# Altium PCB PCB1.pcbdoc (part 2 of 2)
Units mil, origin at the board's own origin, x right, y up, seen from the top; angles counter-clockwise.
Board outline 4044 x 3540 mil, 2 copper layers (Top Layer, Bottom Layer), stack 2.756 mil thick; 143 components, 117 nets, 519 pads, 194 vias.
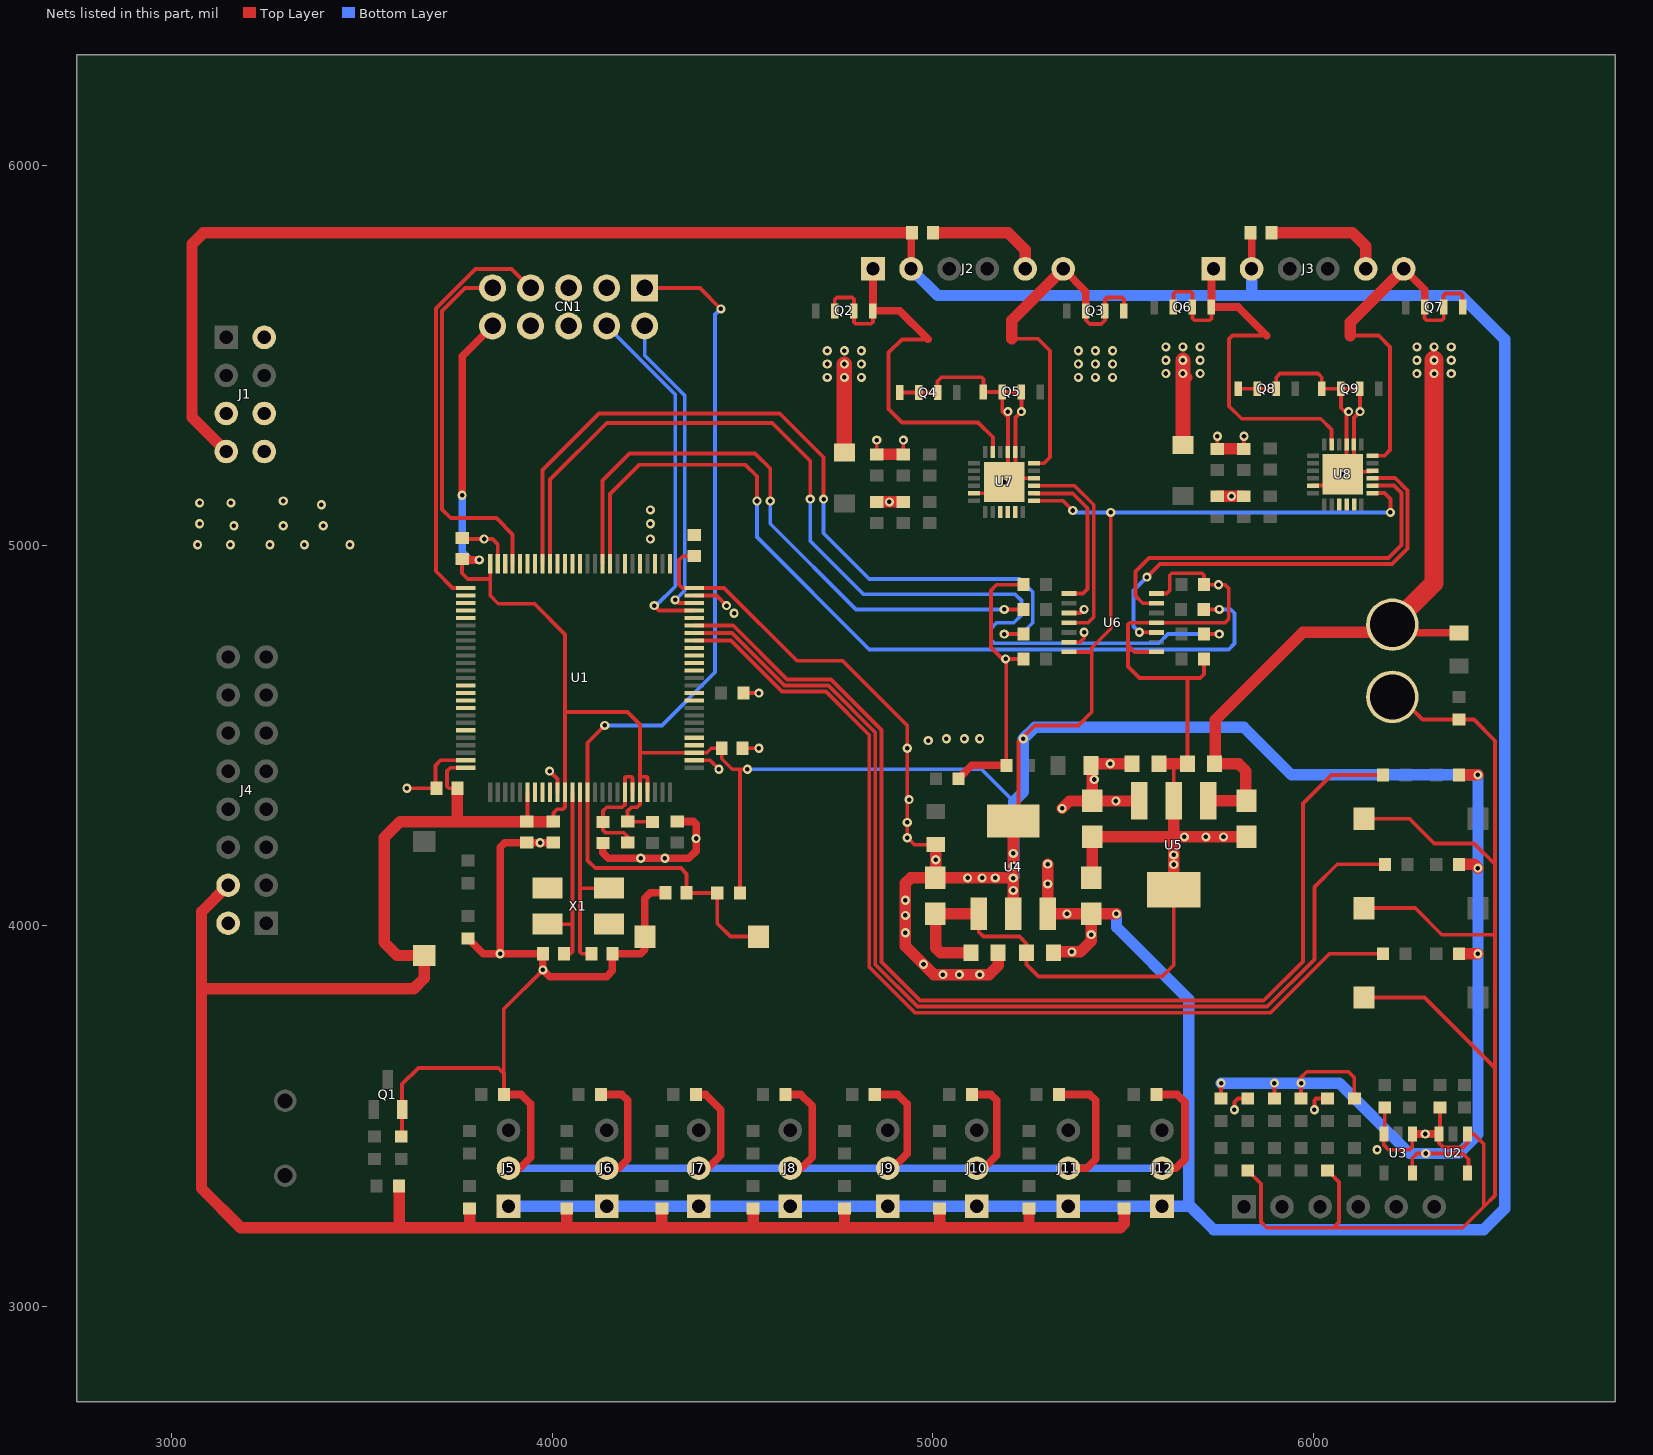
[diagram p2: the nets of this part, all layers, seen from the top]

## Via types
v1: diameter 24.02, hole 12.01, Top Layer to Bottom Layer, 194 vias

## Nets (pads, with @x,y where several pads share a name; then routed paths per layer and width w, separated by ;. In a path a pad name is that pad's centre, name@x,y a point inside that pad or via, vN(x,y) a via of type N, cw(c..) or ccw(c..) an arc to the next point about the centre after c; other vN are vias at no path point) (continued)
GND: C1.2 C2.1 C3.2 C4.2 C5.2 C6.2 C7.2 C8.1 C9.1 C10.1 C12.2 C13.2 C14.2 C15.1 C16.1 C17.2 C18.1 C19.2 C20.2 C21.1 C22.1 C23.1 C26.2 C27.2 C28.1 C29.1 C32.2 C33.2 CN1.6 CN1.8 CN2.1 J1.5 J1.6 J2.5 J3.5 J4.2 J5.2 J6.2 J7.2 J8.2 J9.2 J10.2 J11.2 J12.2 L1.1 Q1.2 Q4.1 Q4.2 Q4.3 Q5.1 Q5.2 Q5.3 Q8.1 Q8.2 Q8.3 Q9.1 Q9.2 Q9.3 R1.1 R4.2 R7.1 R8.2 R11.1 R16.1 R17.1 R18.1 R25.2 R26.1 R27.2 R28.1 R35.1 R36.1 R37.1 R44.1 R45.1 R46.1 R53.1 R54.1 R55.1 R62.1 R63.1 R64.1 SW2.2 SW3.1 SW4.1 SW5.1 U1.10 U1.27 U1.49 U1.74 U1.99 U2.1 U2.3 U3.1 U3.3 U4.1 U5.2 U5.4 U6.1 U6.4 U6.7 U6.10 U6.13 U7.5 U7.16 U7.20 U7.21 U7.25 U8.5 U8.16 U8.20 U8.21 U8.25 | length 19107.5
  Top Layer w10: R11.1@3603,3447 3605.4,3449.4 Q1.2@3605.4,3517.63 3605.4,3584.4 3648,3627 3858,3627 3872.66,3612.34 ; v1(3618,4362) C5.2@3695.44,4362 3693,4364.44 3693,4422 3706.46,4435.46 U1.99@3772.67,4435.46 ; C1.2@3763,5019.56 3765.56,5017 v1(3820.68,5017) 3843,5017 3856.47,5003.53 U1.74@3856.47,4952.33 ; v1(3975.44,3884.56) 3872.66,3781.78 3872.66,3612.34 ; v1(3993,4407) 4013.95,4386.05 U1.10@4013.95,4351.67 ; U1.27@4373.33,4435.46 4414.54,4435.46 v1(4438,4412) ; U1.49@4373.33,4868.53 4431.47,4868.53 v1(4458,4842) ; C4.2@4500.56,4467 v1(4543,4467) ; R7.1@4502.66,4612 v1(4543,4612) ; C23.1@4852.63,5239.44 4853,5239.81 v1(4853,5277) ; Q4.1@4912.63,5402 Q4.2@4962.63,5402 Q4.3@5012.63,5402 5012.63,5431.63 5023,5442 5128,5442 5133,5437 5133,5403.87 Q5.1@5132.63,5403.5 Q5.2@5182.63,5403.5 ; C22.1@4922.63,5239.44 4922.63,5276.63 v1(4923,5277) ; U7.5@5108.95,5137.37 5158.12,5137.37 v1(5187.63,5166.88) 5197.52,5176.77 U7.16@5266.43,5176.77 ; U4.1@5121.02,4032.09 5121.02,3983.98 5133,3972 5228,3972 5246.57,3953.43 C15.1@5246.57,3929.09 5246.57,3898.43 5278,3867 5603,3867 5633.41,3897.41 U5.4@5633.41,4095.2 ; R17.1@5193.34,4422 5193.34,4691.66 v1@5183,4702 ; R26.1@5238.34,4702 v1@5183,4702 ; R28.1@5238.34,4897 5168,4897 5153,4882 5153,4732 v1@5183,4702 ; U6.13@5357.84,4745.82 5386.82,4745.82 5398,4757 v1(5398,4772) ; U6.10@5357.84,4822.59 5388.59,4822.59 v1(5398,4832) ; U6.1@5588.16,4720.23 5529.77,4720.23 5513,4737 ; U6.7@5588.16,4873.77 5614.77,4873.77 5623,4882 5623,4922 5628,4927 5708,4927 5713,4922 5713,4897.34 R27.2@5712.66,4897 v1(5751.12,4897) 5768,4897 5778,4887 5778,4807 5768,4797 U6.4@5588.16,4797 5518,4797 5513,4792 5513,4737 ; 5631.97,4426.25 5633.41,4424.81 U5.2@5633.41,4329.05 ; C18.1@5669.2,4426.25 5669.2,4649.8 5666.99,4652 ; R25.2@5712.66,4702 5712.66,4661.66 5703,4652 5666.99,4652 ; C29.1@5747.42,5253.83 5748,5254.41 v1(5748,5287) ; v1(5793,3517) 5793,3537 5802.66,3546.66 R55.1@5828,3546.66 ; Q8.1@5802.63,5412 Q8.2@5852.63,5412 Q8.3@5902.63,5412 5902.63,5441.63 5913,5452 6013,5452 6022.63,5442.37 Q9.1@6022.63,5412 Q9.2@6072.63,5412 ; C28.1@5817.42,5253.83 5817.42,5286.42 v1(5818,5287) ; R62.1@5828,3357.34 5863,3322.34 5863,3222 5878,3207 6053,3207 ; U8.5@5998.89,5157.33 6048.06,5157.33 v1(6077.57,5186.84) U8.25@6084.72,5193.99 ; v1(6003,3517) 6003,3542 6007.66,3546.66 R64.1@6038,3546.66 ; R63.1@6038,3357.34 6068,3327.34 6068,3222 6053,3207 ; SW3.1@6133.4,3812 6292.41,3812 6478,3626.41 ; SW4.1@6133.4,4047 6268,4047 6338,3977 6478,3977 ; SW5.1@6133.4,4282 6253,4282 6318,4217 6423,4217 6478,4162 ; U8.16@6156.37,5196.73 6153.63,5193.99 U8.25@6084.72,5193.99 ; R8.2@6188,3522.34 6188,3455.59 U3.3@6185.6,3453.18 6185.6,3424.4 6198,3412 6253,3412 6260.4,3419.4 U3.1@6260.4,3453.18 ; CN2.1@6208,4622 6287.66,4542.34 R16.1@6383,4542.34 6422.66,4542.34 6478,4487 6478,4162 ; R4.2@6333,3522.68 6333,3455.59 U2.3@6330.6,3453.18 6330.6,3429.4 6342,3418 6394,3418 6405.4,3429.4 U2.1@6405.4,3453.18 6421.81,3453.18 6448,3427 6448,3262 ; 3872.66,3612.34 R35.1@3872.66,3557 3873,3557.34 3873,3612 3872.66,3612.34 ; Q5.2@5182.63,5403.5 Q5.3@5232.63,5403.5 5233,5403.13 v1(5233,5352) 5217.21,5336.21 U7.20@5217.21,5245.68 5217.21,5196.46 5197.56,5176.81 U7.21@5197.56,5245.68 5197.56,5337.44 5182.63,5352.37 Q5.2@5182.63,5403.5 ; 5513,4737 5513,4682 5543,4652 5666.99,4652 ; 6053,3207 6393,3207 6448,3262 ; Q9.2@6072.63,5412 Q9.3@6122.63,5412 6123,5411.63 v1(6123,5352) 6107.15,5336.15 U8.20@6107.15,5265.64 6107.15,5216.42 U8.25@6087.5,5196.77 ; Q9.2@6072.63,5412 6073,5411.63 6073,5362 6087.5,5347.5 U8.21@6087.5,5265.64 U8.25@6087.5,5196.77 ; U8.25@6084.72,5193.99 U8.25@6087.5,5196.77 ; 6448,3262 6478,3292 6478,3626.41 ; 6478,3626.41 6478,3977 ; 6478,3977 6478,4162
  Top Layer w20: R1.1@3778,3967.34 3818.34,3927 v1(3863,3927) ; R35.1@3872.66,3557 3918,3557 3943,3532 3943,3392 3914.15,3363.15 J5.2@3885,3363.15 ; C7.2@4003,4218.83 v1(3967.93,4218.83) C6.2@3933,4218.83 3874.83,4218.83 3863,4207 v1(3863,3927) ; R36.1@4128,3557 4183,3557 4198,3542 4198,3387 4174.15,3363.15 J6.2@4143.42,3363.15 ; L1.1@4133,4218.18 4133,4192 4147,4178 v1(4232.58,4178) v1(4295.89,4178) 4359,4178 4378,4197 v1(4378,4229.95) 4378,4267 4370.44,4274.56 C12.2@4328,4274.56 ; C13.2@4298,4087 4258,4087 4243.4,4072.4 SW2.2@4243.4,3972 4243.4,3937.4 4233,3927 C8.1@4158.12,3927 4158.12,3882.12 4143,3867 3993,3867 v1(3975.44,3884.56) C2.1@3975.44,3927 v1(3863,3927) ; R37.1@4377.32,3557 4403,3557 4443,3517 4443,3397 4409.15,3363.15 J7.2@4384.57,3363.15 ; R44.1@4612.66,3557 4653,3557 4683,3527 4683,3392 4654.15,3363.15 J8.2@4625.72,3363.15 ; R45.1@4847.66,3557 4908,3557 4933,3532 4933,3402 4894.15,3363.15 J9.2@4881.61,3363.15 ; R18.1@5067.66,4387 5102.66,4422 R17.1@5193.34,4422 ; R46.1@5102.66,3557 5153,3557 5168,3542 5168,3397 5134.15,3363.15 J10.2@5115.29,3363.15 ; R53.1@5332.32,3557 5413,3557 5428,3542 5428,3387 5404.15,3363.15 J11.2@5356.43,3363.15 ; R54.1@5587.66,3557 5643,3557 5663,3537 5663,3387 5639.15,3363.15 J12.2@5602.58,3363.15 ; U3.1@6260.4,3453.18 v1(6294.63,3453.18) U2.3@6330.6,3453.18
  Top Layer w30: C27.2@4852.63,5114.44 v1(4885.89,5114.44) C26.2@4922.63,5114.44 ; C23.1@4852.63,5239.44 C22.1@4922.63,5239.44 ; C9.1@5000.56,5822 5198,5822 5243,5777 J2.5@5243,5727 ; C16.1@5101.14,3929.09 5020.9,3929.09 5008,3942 5008,4030.43 C17.2@5006.57,4031.86 5120.78,4031.86 U4.1@5121.02,4032.09 ; C14.2@5416.57,4126.34 5419.63,4129.4 C20.2@5419.63,4234.01 5633.41,4234.01 ; C21.1@5594.63,4426.25 5631.97,4426.25 C18.1@5669.2,4426.25 ; U5.4@5633.41,4095.2 v1(5633.41,4161.53) v1(5633.41,4186.96) 5633.41,4234.01 ; U5.2@5633.41,4329.05 5633.41,4234.01 ; C29.1@5747.42,5253.83 C28.1@5817.42,5253.83 ; C33.2@5747.63,5129.44 v1(5785.22,5129.44) C32.2@5817.63,5129.44 ; C19.2@5824.63,4234.01 v1(5764.16,4234.01) v1(5717.98,4234.01) v1(5661.42,4234.01) 5633.41,4234.01 ; C10.1@5890.56,5822 6103,5822 6138,5787 J3.5@6138,5727
  Bottom Layer w20: J5.2@3885,3363.15 J6.2@4143.42,3363.15 J7.2@4384.57,3363.15 J8.2@4625.72,3363.15 J9.2@4881.61,3363.15 J10.2@5115.29,3363.15 J11.2@5356.43,3363.15 J12.2@5602.58,3363.15
  other v1: 6168,3412 5191.63,4702 4478,4822 3068,5002 3154.04,5002 3257.83,5002 3348.65,5002 3468.02,5002 4258,5017 3163,5052 3293,5052 3398,5052 3073,5057 4258,5057 4258,5093.44 3393,5107 3073,5112 3155.33,5112 3293,5117 5197.56,5351.89 6093,5352
KEY-1: R14.1 U1.43 | length 2636.8
  Top Layer w10: U1.43@4373.33,4750.42 4469.58,4750.42 4604,4616 4719,4616 4833,4502 4833,3892 4953,3772 5888,3772 6043,3927 R14.1@6183.34,3927
KEY-2: R13.1 U1.44 | length 2845.4
  Top Layer w10: U1.44@4373.33,4770.11 4472.52,4770.11 4610.63,4632 4725.63,4632 4849,4508.63 4849,3898.63 4959.63,3788 5879,3788 6003,3912 6003,4102 6063,4162 R13.1@6188.34,4162
KEY-3: R12.1 U1.45 | length 3064.4
  Top Layer w10: U1.45@4373.33,4789.79 4475.46,4789.79 4617.25,4648 4732.25,4648 4865,4515.25 4865,3905.25 4966.25,3804 5870,3804 5973,3907 5973,4322 6048,4397 R12.1@6183.34,4397
L_A: J3.1 Q6.1 Q6.2 Q6.3 U8.23 | length 1129.5
  Top Layer w10: Q6.3@5632.63,5626.77 5632.63,5661.63 5638,5667 5678,5667 5682.63,5662.37 Q6.2@5682.63,5626.77 5682.63,5597.37 5688,5592 5728,5592 5732.63,5596.63 Q6.1@5732.63,5626.77 ; 5877.63,5551.77 5787.77,5551.77 5779,5543 5779,5366 5812,5333 6019.63,5333 6048.15,5304.48 U8.23@6048.15,5265.64
  Top Layer w20: J3.1@5738,5727 5732.63,5721.63 Q6.1@5732.63,5626.77 5802.63,5626.77 5877.63,5551.77
L_B: J3.6 Q7.1 Q7.2 Q7.3 U8.18 | length 1024.5
  Top Layer w10: 6097.63,5551.77 6172.23,5551.77 6202,5522 6202,5251 6187.08,5236.08 U8.18@6156.37,5236.08 ; Q7.3@6292.63,5626.65 6292.63,5597.37 6298,5592 6338,5592 6343,5597 6343,5626.28 Q7.2@6342.63,5626.65 6342.63,5656.63 6348,5662 6388,5662 6392.63,5657.37 Q7.1@6392.63,5626.65
  Top Layer w20: J3.6@6238,5727 6292.63,5672.37 Q7.3@6292.63,5626.65
  Top Layer w30: 6097.63,5551.77 6097.63,5586.63 J3.6@6238,5727
L_EN: U6.6 U8.14 | length 1076.2
  Top Layer w10: U6.6@5588.16,4848.18 5551.82,4848.18 5533,4867 5533,4932 5568,4967 6198,4967 6232,5001 6232,5138 6212.62,5157.38 U8.14@6156.37,5157.38
L_EN_PWM: R23.1 U1.59 | length 2321.9
  Top Layer w10: U1.59@4151.74,4952.33 4151.74,5135.74 4228,5212 4508,5212 4538,5182 v1(4538,5117) ; R23.1@5712.32,4832 v1(5753,4832)
  Bottom Layer w10: v1(4538,5117) 4538,5022 4833,4727 5778,4727 5793,4742 5793,4822 5783,4832 v1(5753,4832)
L_PH: U6.3 U8.15 | length 1184.9
  Top Layer w10: v1(5543,4772) 5587.57,4772 U6.3@5588.16,4771.41 ; v1(5563,4917) 5597,4951 6207,4951 6248,4992 6248,5144.63 6215.55,5177.08 U8.15@6156.37,5177.08
  Bottom Layer w10: v1(5543,4772) 5528,4787 5528,4882 v1(5563,4917)
L_PH_DIR: R21.1 U1.67 | length 2654.5
  Top Layer w10: U1.67@3994.26,4952.33 3994.26,5173.26 4143,5322 4578,5322 4678,5222 v1(4678,5122) ; R21.1@5712.66,4767 v1(5753,4767)
  Bottom Layer w10: v1(4678,5122) 4678,5012 4818,4872 5216.38,4872 5233,4855.38 5233,4817 5213,4797 5168,4797 5153,4782 5153,4752 5162,4743 5594,4743 5618,4767 v1(5753,4767)
OSC_IN: C2.2 U1.12 X1.1 | length 511.4
  Top Layer w10: X1.1@3987.29,4004.76 4050.76,4004.76 4053.32,4007.32 ; C2.2@4030.56,3927 4048,3927 4053.32,3932.32 4053.32,4007.32 ; U1.12@4053.32,4351.67 4053.32,4007.32
OSC_OUT: C8.2 U1.13 X1.3 | length 528.6
  Top Layer w10: U1.13@4073,4351.67 4073,4102 ; C8.2@4103,3927 4078,3927 4073,3932 4073,4102 ; X1.3@4148.71,4099.24 4075.76,4099.24 4073,4102
PB10: CN1.4 U1.47 | length 945.9
  Top Layer w10: v1(4268,4842) 4280.84,4829.16 U1.47@4373.33,4829.16
  Bottom Layer w10: CN1.4@4143,5577 4323,5397 4323,4892 4273,4842 v1(4268,4842)
PB11: CN1.2 U1.48 | length 827.6
  Top Layer w10: v1(4323,4857) 4331.15,4848.85 U1.48@4373.33,4848.85
  Bottom Layer w10: CN1.2@4243,5577 4243,5499.63 4348,5394.63 4348,4882 v1(4323,4857)
R_A: J2.1 Q2.1 Q2.2 Q2.3 U7.23 | length 1125.5
  Top Layer w10: Q2.3@4742.63,5616.77 4742.63,5646.63 4748,5652 4788,5652 4792.63,5647.37 Q2.2@4792.63,5616.77 4792.63,5587.37 4797,5583 4838,5583 4842.63,5587.63 Q2.1@4842.63,5616.77 ; 4987.63,5541.77 4918.77,5541.77 4884,5507 4884,5358.63 4919.63,5323 5119.63,5323 5118.57,5322 5120.63,5322 5158.21,5284.42 U7.23@5158.21,5245.68
  Top Layer w20: J2.1@4843,5727 4843,5617.13 Q2.1@4842.63,5616.77 4912.63,5616.77 4987.63,5541.77
R_B: J2.6 Q3.1 Q3.2 Q3.3 U7.18 | length 1039.2
  Top Layer w10: 5207.63,5543.27 5276.73,5543.27 5308,5512 5308,5232 5292.12,5216.12 U7.18@5266.43,5216.12 ; Q3.3@5402.63,5616.77 5402.63,5592 5412.63,5582 5443,5582 5453,5592 5453,5616.4 Q3.2@5452.63,5616.77 5452.63,5646.63 5458,5652 5498,5652 5502.63,5647.37 Q3.1@5502.63,5616.77
  Top Layer w20: J2.6@5343,5727 5402.63,5667.37 Q3.3@5402.63,5616.77
  Top Layer w30: 5207.63,5543.27 5207.63,5591.63 J2.6@5343,5727
R_EN: U6.8 U7.14 | length 423.1
  Top Layer w10: U7.14@5266.43,5137.42 5266.85,5137 5368,5137 5407,5098 5407,4886 5394.77,4873.77 U6.8@5357.84,4873.77
R_EN_PWM: R24.2 U1.60 | length 1609.2
  Top Layer w10: U1.60@4132.06,4952.33 4132.06,5171.06 4203,5242 4533,5242 4573,5202 v1(4573,5117) ; v1(5188,4832) R24.2@5238.34,4832
  Bottom Layer w10: v1(4573,5117) 4573,5057 4798,4832 v1(5188,4832)
R_PH: U6.11 U7.15 | length 543.7
  Top Layer w10: U7.15@5266.43,5157.12 5372.88,5157.12 5423,5107 5423,4812 5408,4797 U6.11@5357.84,4797
R_PH_DIR: R22.2 U1.68 | length 2126
  Top Layer w10: U1.68@3974.58,4952.33 3974.58,5198.58 4123,5347 4598,5347 4713,5232 v1(4713,5122) ; v1(5188,4767) R22.2@5238.34,4767
  Bottom Layer w10: v1(4713,5122) 4713,5032 4833,4912 5228.46,4912 5263,4877.46 5263,4797 5233,4767 v1(5188,4767)
RST: C13.1 CN1.1 R3.1 SW2.1 U1.14 | length 2514.8
  Top Layer w10: v1(4138,4527) 4092.69,4481.69 U1.14@4092.69,4351.67 4092.69,4172.31 4113,4152 4338,4152 4353,4137 4353,4087.12 C13.1@4353.12,4087 R3.1@4433.68,4087 4433.68,4006.32 4468,3972 SW2.1@4542.6,3972 ; CN1.1@4243,5677 4388,5677 v1(4443,5622)
  Bottom Layer w10: v1(4138,4527) 4288,4527 4428,4667 4428,5607 v1(4443,5622)
SWCLK: CN1.7 U1.76 | length 1100.5
  Top Layer w10: U1.76@3772.67,4888.22 3738,4888.22 3694,4932.22 3694,5623 3798,5727 3893,5727 CN1.7@3943,5677
SWDIO: CN1.9 U1.72 | length 969.4
  Top Layer w10: CN1.9@3843,5677 3770.63,5677 3710,5616.37 3710,5095 3733,5072 3853,5072 3895.84,5029.16 U1.72@3895.84,4952.33
VCC: C18.2 C19.1 CN2.2 D1.1 D2.1 LED1.2 U5.1 | length 2334.5
  Top Layer w20: CN2.2@6208,4772 6209.69,4770.31 LED1.2@6383,4770.31
  Top Layer w30: v1(5657.63,5452) 5668,5441.63 ; U5.1@5723.96,4329.05 C19.1@5824.07,4329.05 ; C19.1@5824.63,4328.49 C19.1@5824.07,4329.05 ; CN2.2@6208,4772 5973,4772 5743,4542 5743,4429.19 C18.2@5740.07,4426.25 5803.75,4426.25 5823,4407 5823,4330.13 C19.1@5824.07,4329.05
  Top Layer w40: D1.1@4767.63,5243.81 v1(4767.63,5442) v1(4767.63,5477) ; D2.1@5657.63,5263.81 v1(5657.63,5452) v1(5657.63,5487)
  Top Layer w50: CN2.2@6208.01,4792 6317.63,4901.63 v1(6317.63,5451.88) v1(6317.63,5486.88)
  other v1: 4722.63,5442 4812.63,5442 5382.63,5442 5427.63,5442 5472.63,5442 5612.63,5452 5702.63,5452 6272.63,5451.88 6362.63,5451.88 4722.63,5477 4812.63,5477 5382.63,5477 5427.63,5477 5472.63,5477 5612.63,5487 5702.63,5487 6272.63,5486.88 6362.63,5486.88 4722.63,5512 4767.63,5512 4812.63,5512 5382.63,5512 5427.63,5512 5472.63,5512 5612.63,5522 5657.63,5522 5702.63,5522 6272.63,5521.88 6317.63,5521.88 6362.63,5521.88
VCC3V3: C1.1 C3.1 C4.1 C5.1 C6.1 C7.1 C11.1 C16.2 C17.1 CN1.10 J4.4 L2.2 LED3.2 R3.2 R6.1 R15.1 R19.1 R20.1 R29.2 R30.2 R31.2 R38.2 R39.2 R40.2 R47.2 R48.2 R49.2 R56.2 R57.2 R58.2 SW1.2 U1.6 U1.11 U1.21 U1.22 U1.28 U1.50 U1.75 U1.100 U2.5 U3.5 U4.2 U4.4 U6.14 U7.13 U8.13 | length 17825.9
  Top Layer w10: 3078,3834.93 3080.07,3837 ; C5.1@3750.56,4362 3728,4362 3723,4367 3723,4407 3731.78,4415.78 U1.100@3772.67,4415.78 ; C1.1@3763,4964.44 3763,4927 3778,4912 3834.95,4912 3836.78,4913.83 ; U1.75@3836.78,4952.33 3836.78,4913.83 ; C6.1@3929.95,4277 C6.1@3933,4273.95 3935.21,4276.16 U1.6@3935.21,4351.67 ; C7.1@3996.6,4273.95 C7.1@4003,4280.35 ; C7.1@4003,4273.95 C7.1@4003,4280.35 ; U1.22@4250.17,4351.67 4250.17,4389.83 4248,4392 4233,4392 4230.48,4389.48 ; L2.2@4263,4273.29 4262.34,4273.95 C11.1@4198,4273.95 4198,4302 4208,4312 4223,4312 4230.48,4319.48 U1.21@4230.48,4351.67 4230.48,4389.48 ; C3.1@4373,4971.88 4342.88,4971.88 4333,4962 4333,4897 4341.78,4888.22 U1.50@4373.33,4888.22 4451.78,4888.22 4643,4697 4763,4697 4933,4527 v1(4933,4466.93) v1(4933,4272.31) v1(4933,4232) 4951.31,4213.69 LED3.2@5008,4213.69 ; R3.2@4493,4087 4493,4411.05 4492.05,4412 ; v1(4513,4412) 4492.05,4412 ; U4.4@5211.57,4276.1 5225.78,4290.31 5225.78,4484.78 5268,4527 5383,4527 5418,4562 5418,4717 ; U7.13@5266.43,5117.72 5342.28,5117.72 v1(5368,5092) ; U6.14@5357.84,4720.23 5414.77,4720.23 5418,4717 ; v1(5468,5087) 5468,4781.14 5418,4731.14 5418,4717 ; R49.2@5758,3546.66 v1(5758,3587) ; R56.2@5898,3546.66 v1(5898,3587) ; R57.2@5968,3547 v1(5968,3587) 5968,3602 5983,3617 6093,3617 6108,3602 R58.2@6108,3546.66 ; U8.13@6156.37,5137.68 6187.32,5137.68 6203,5122 v1(6203,5087) ; U3.5@6260.4,3350.82 6260.4,3389.4 6273,3402 v1(6295.7,3402) 6393,3402 6408,3387 6408,3353.41 U2.5@6405.4,3350.82 ; 3836.78,4913.83 3836.78,4868.22 3858,4847 3953,4847 4033.63,4766.37 4033.63,4562 ; C7.1@4003,4280.35 4003,4297 4013,4307 4028,4307 4033.63,4312.63 U1.11@4033.63,4351.67 4033.63,4562 ; 4033.63,4562 4198,4562 4230.48,4529.52 4230.48,4454.48 ; 4230.48,4389.48 4230.48,4454.48 ; 4230.48,4454.48 4231.15,4455.15 U1.28@4373.33,4455.15 4406.15,4455.15 4418,4467 C4.1@4445.44,4467 4445.44,4439.56 4473,4412 4492.05,4412
  Top Layer w20: R6.1@3597.66,3317 R6.1@3598,3316.66 ; C1.1@3763,4964.44 3765.44,4962 v1(3808,4962) ; v1(3763,5132) 3763,5497 CN1.10@3843,5577
  Top Layer w30: J4.4@3148,4107 3078,4037 3078,3834.93 ; R6.1@3597.66,3317 3597.66,3208.31 3598.97,3207 ; C5.1@3750.56,4362 3750.56,4284.44 3761.05,4273.95 ; R29.2@3783,3257.68 3783,3207 ; C7.1@4003,4273.95 3996.6,4273.95 C6.1@3933,4273.95 3761.05,4273.95 ; R30.2@4038,3257.68 4038,3207 ; R31.2@4288,3257.68 4288,3207 ; R38.2@4528,3257.68 4528,3207 ; R39.2@4768,3257.68 4768,3207 ; LED3.2@5008,4213.69 v1(5008,4174.17) 5008,4127.77 C17.1@5006.57,4126.34 ; R40.2@5018,3257.68 5018,3207 ; C16.2@5172.01,3929.09 5172.01,3896.01 5148,3872 v1(5123.62,3872) v1(5069.99,3872) v1(5026.74,3872) 5003,3872 v1(4975.66,3899.34) 4928,3947 v1(4928,3982.15) v1(4928,4027.7) v1(4928,4067.49) 4928,4112 4942.34,4126.34 C17.1@5006.57,4126.34 ; U4.2@5211.57,4032.09 v1(5211.57,4093.32) v1(5211.57,4125.97) ; U4.4@5211.57,4276.1 v1(5211.57,4190.86) v1(5211.57,4157.26) v1(5211.57,4125.97) ; R47.2@5253,3257.68 5253,3207 ; R48.2@5503,3257.68 5503,3217 5493,3207 5253,3207 ; R15.1@6382.66,3927 v1(6433,3927) ; R19.1@6382.66,4162 6423,4162 v1(6433,4152) ; R20.1@6382.66,4397 v1(6433,4397) ; 3078,3834.93 3078,3310.07 3181.07,3207 3598.97,3207 ; 3078,3834.93 3635.93,3834.93 3663,3862 SW1.2@3663,3922.4 3592.6,3922.4 3558,3957 3558,4232 3599.95,4273.95 3761.05,4273.95 ; 3598.97,3207 3783,3207 ; 3783,3207 4038,3207 ; 4038,3207 4288,3207 ; 4288,3207 4528,3207 ; 4528,3207 4768,3207 ; 4768,3207 5018,3207 ; C17.1@5006.57,4126.34 v1(5091.69,4126.34) v1(5129.75,4126.34) v1(5164.35,4126.34) 5211.2,4126.34 v1(5211.57,4125.97) ; 5018,3207 5253,3207
  Bottom Layer w10: v1(4513,4412) 5128,4412 5213,4327 ; v1(5368,5092) 5373,5087 v1(5468,5087) v1(6203,5087)
  Bottom Layer w20: v1(3763,5132) 3763,4982 3783,4962 v1(3808,4962)
  Bottom Layer w30: v1(5211.57,4125.97) 5213,4127.4 5213,4327 5238,4352 v1(5238,4492) 5268,4522 5818,4522 5943,4397 v1(6433,4397) v1(6433,4152) v1(6433,3927) 6433,3452 6383,3402 v1(6295.7,3402) 6253.27,3402 6068.27,3587 v1(5968,3587) v1(5898,3587) v1(5758,3587)
  other v1: 4938,4332 4988,4487 5035.76,4492 5083,4492 5123,4492
VCC5V: C9.2 C10.2 C14.1 C15.2 C20.1 C21.2 J1.7 J2.2 J3.2 J5.1 J6.1 J7.1 J8.1 J9.1 J10.1 J11.1 J12.1 LED2.2 U4.3 U5.3 | length 11096.6
  Top Layer w20: J2.2@4943,5727 4943,5819.56 C9.2@4945.44,5822 ; v1(5482.85,4031.86) v1@5483,4032 ; C10.2@5835.44,5822 5838,5819.44 J3.2@5838,5727
  Top Layer w30: J1.7@3143,5247 3053,5337 3053,5792 3083,5822 C9.2@4945.44,5822 ; v1(5302.12,4162.43) v1(5302.12,4110.74) U4.3@5302.12,4032.09 5302.36,4031.86 v1(5352.95,4031.86) C14.1@5416.57,4031.86 ; C15.2@5317.44,3929.09 5320.35,3932 v1(5365.55,3932) 5388,3932 5416.57,3960.57 v1(5416.57,3977.33) C14.1@5416.57,4031.86 ; v1(5339.98,4308.98) 5359.49,4328.49 C20.1@5419.63,4328.49 ; v1(5482.85,4031.86) C14.1@5416.57,4031.86 ; C21.2@5523.76,4426.25 v1(5466.49,4426.25) 5420.56,4426.25 LED2.2@5416.31,4422 5419.63,4418.68 C20.1@5419.63,4328.49 ; U5.3@5542.86,4329.05 5542.3,4328.49 v1(5481.35,4328.49) C20.1@5419.63,4328.49
  Bottom Layer w30: J5.1@3885,3263.15 J6.1@4143.42,3263.15 J7.1@4384.57,3263.15 J8.1@4625.72,3263.15 J9.1@4881.61,3263.15 J10.1@5115.29,3263.15 J11.1@5356.43,3263.15 J12.1@5602.58,3263.15 5673,3263.15 ; J2.2@4943,5727 5013,5657 5843,5657 ; v1(5482.85,4031.86) 5482.85,3997.14 5673,3807 5673,3263.15 ; J3.2@5838,5727 5838,5662 5843,5657 ; 5673,3263.15 5676.85,3263.15 5738,3202 6448,3202 6503,3257 6503,5542 6388,5657 5843,5657
  other v1: 5424.57,4384.99
VREF-: C11.2 L1.2 U1.19 U1.20 | length 333.4
  Top Layer w10: C11.2@4198,4218.83 4198,4234.93 4188,4244.93 4140.07,4244.93 4133,4252 L1.2@4133,4273.29 4133,4302 4143,4312 4183.77,4312 4191.11,4319.34 U1.19@4191.11,4351.67 4191.11,4390.11 4193,4392 4208,4392 4210.8,4389.2 U1.20@4210.8,4351.67
"": CN1.3 CN1.5 J1.2 J1.8 U1.7 U1.8 U1.9 U1.29 U1.30 U1.35 U1.36 U1.39 U1.40 U1.41 U1.42 U1.46 U1.51 U1.53 U1.55 U1.57 U1.63 U1.64 U1.65 U1.66 U1.69 U1.70 U1.71 U1.73 U1.77 U1.78 U1.79 U1.80 U1.89 U1.90 U1.91 U1.92 U1.95 U7.9 U7.10 U7.11 U8.9 U8.10 U8.11 X1.2 X1.4

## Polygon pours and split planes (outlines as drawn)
VCC3V3 on Top Layer (solid, remove dead copper, pour order 4): 3810.7,4387.94 4327,4387.94 4327,4912.04 3810.7,4912.04
GND on Bottom Layer (solid, remove dead copper, pour order 7): 3000,3168 6544,3168 6544,5864.9 3000,5864.9
GND on Top Layer (solid, remove dead copper, pour order 8): 3000,3168 6544,3168 6544,5864.9 3000,5864.9
VCC5V on Top Layer (solid, remove dead copper, pour order 0): 5277.98,3907.02 5276.19,4430.19 5318,4472 5534.67,4472 5573,4439.14 5573,3902 5283,3902
VCC3V3 on Top Layer (solid, remove dead copper, pour order 1): 4983,3847 4893,3937 4893,4507 4913,4527 5253.71,4527 5265.86,4514.86 5265.86,3901.38 5211.57,3847.09 4983.09,3847.09
VCC3V3 on Bottom Layer (solid, remove dead copper, pour order 2): 4983,3847 4893,3937 4893,4507 4913,4527 5253.71,4527 5253.71,3889.23 5211.57,3847.09 4983.09,3847.09
VCC5V on Bottom Layer (solid, remove dead copper, pour order 3): 5277.98,3912.02 5276.19,4435.19 5318,4477 5534.67,4477 5573,4444.14 5573,3907 5283,3907
VCC on Top Layer (solid, remove dead copper, pour order 5): 5698,4277 5698,4592 5968,4862 6252.38,4862 6293,4847 6293,4742 6280.86,4704.86 6135.6,4704.86 5858,4427.26 5858,4277
VCC on Bottom Layer (solid, remove dead copper, pour order 6): 4667.63,5536.63 4693,5562 6388,5562 6408,5542 6408,5402 6393,5387 4686.1,5387 4667.63,5405.46 4667.63,5536.62

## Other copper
Top Layer:
  drawing of 470 lines, arcs and shapes, not listed
Bottom Layer:
  region net D0: 3171.25,4727.5 3153,4759.7 3143,4759.7 3124.75,4727.5
  region net E7: 3268.5,4683.75 3300.7,4702 3300.7,4712 3268.5,4730.25
  region net D4: 3178.94,4605.06 3188.8,4640.73 3181.73,4647.8 3146.06,4637.94
  region net E6: 3259.91,4578.38 3298.56,4592 3301.97,4602 3274.91,4622.39
  region net E5: 3268.5,4483.75 3300.7,4502 3300.7,4512 3268.5,4530.25
  region net E4: 3268.5,4383.75 3290.63,4402 3290.63,4412 3268.5,4430.25
  region net B15: 3149.94,4337.94 3114.27,4347.8 3107.2,4340.73 3117.06,4305.06
  region net E3: 3271.25,4327.5 3253,4341.75 3243,4341.75 3224.75,4327.5
  region net B13: 3149.94,4237.94 3114.27,4247.8 3107.2,4240.73 3117.06,4205.06
  region net E2: 3278.94,4205.06 3288.8,4240.73 3281.73,4247.8 3246.06,4237.94
  region net ENCODER_L-B: 6061.25,5747.5 6043,5767 6033,5767 6014.75,5747.5
  region net ENCODER_L-A: 5961.25,5747.5 5943,5779.7 5933,5779.7 5914.75,5747.5
  region net VCC5V: 5814.75,5706.5 5823,5674.3 5853,5674.3 5861.25,5706.5
  region net ENCODER_R-B: 5144.94,5757.94 5109.27,5767.8 5102.2,5760.73 5112.06,5725.06
  region net ENCODER_R-A: 5041.4,5757.96 5006.41,5765.66 5000.15,5757.78 5012.48,5721.54
  region net VCC5V: 4941.06,5696.06 4969.66,5679.13 4990.87,5700.34 4973.94,5728.94
  region net PB10: 4140.78,5541.64 4182.06,5530.87 4189.13,5537.94 4178.36,5579.22
  region net PB11: 4216.43,5553.56 4238,5516.76 4248,5516.76 4269.57,5553.56
  region net VCC5V: 5526.58,3248.15 5571.58,3232.15 5571.58,3294.15 5526.58,3278.15
  region net VCC5V: 5673,3248.15 5673,3278.15 5633.58,3294.15 5633.58,3232.15
  region net VCC5V: 5432.43,3248.15 5432.43,3278.15 5387.43,3294.15 5387.43,3232.15
  region net VCC5V: 5280.43,3248.15 5325.43,3232.15 5325.43,3294.15 5280.43,3278.15
  region net VCC5V: 5191.29,3248.15 5191.29,3278.15 5146.29,3294.15 5146.29,3232.15
  region net VCC5V: 5039.29,3248.15 5084.29,3232.15 5084.29,3294.15 5039.29,3278.15
  region net VCC5V: 4701.72,3248.15 4701.72,3278.15 4656.72,3294.15 4656.72,3232.15
  region net VCC5V: 4549.72,3248.15 4594.72,3232.15 4594.72,3294.15 4549.72,3278.15
  region net VCC5V: 4308.57,3248.15 4353.57,3232.15 4353.57,3294.15 4308.57,3278.15
  region net VCC5V: 4460.57,3248.15 4460.57,3278.15 4415.57,3294.15 4415.57,3232.15
  region net VCC5V: 4219.42,3248.15 4219.42,3278.15 4174.42,3294.15 4174.42,3232.15
  region net VCC5V: 4067.42,3248.15 4112.42,3232.15 4112.42,3294.15 4067.42,3278.15
  region net VCC5V: 3961,3248.15 3961,3278.15 3916,3294.15 3916,3232.15
  region net VCC5V: 4805.61,3248.15 4850.61,3232.15 4850.61,3294.15 4805.61,3278.15
  region net VCC5V: 4957.61,3248.15 4957.61,3278.15 4912.61,3294.15 4912.61,3232.15
  region net D4: 3693.75,4733.98 3682.1,4739.97 3675.03,4732.9 3681.02,4721.25
  region net D0: 3700.66,4816.24 3689.9,4827.18 3677.67,4825.26 3682.87,4813.45
  region net E2: 3815.06,4491.01 3805.37,4487 3805.37,4477 3815.06,4472.99
  region net E3: 3815.06,4526.01 3802.59,4522 3802.59,4512 3815.06,4507.99
  region net E4: 3823.75,4563.98 3813.54,4568.54 3806.46,4561.46 3811.02,4551.25
  region net E5: 3815.06,4601.01 3802.59,4597 3802.59,4587 3815.06,4582.99
  region net E6: 3815.06,4641.01 3802.59,4637 3802.59,4627 3815.06,4622.99
  region net B13: 4270.06,4896.01 4257.59,4892 4257.59,4882 4270.06,4877.99
  region net B15: 4210.06,4871.01 4197.59,4867 4197.59,4857 4210.06,4852.99
  region net E7: 4315.06,4661.01 4302.59,4657 4302.59,4647 4315.06,4642.99
  region net $2N7136: 6013.22,5105.72 6025.69,5109.72 6025.69,5119.72 6013.22,5123.73
  region net $2N7136: 6147.31,5122.57 6133.84,5119.72 6131.51,5109.72 6143.22,5105.03
  region net $2N7132: 5123.75,5085.19 5136.22,5089.2 5136.22,5099.2 5123.75,5103.2
  region net $2N7132: 5256.84,5102.31 5243.58,5099.2 5241.71,5089.2 5253.54,5084.6
  region net L_PH: 5551.02,4917.75 5545.03,4906.1 5552.1,4899.03 5563.75,4905.02
  region net L_PH: 5543.75,4783.98 5532.1,4789.97 5525.03,4782.9 5531.02,4771.25
  region net ENCODER_L-B: 3895.94,4772.99 3908.41,4777 3908.41,4787 3895.94,4791.01
  region net ENCODER_L-A: 3855.94,4747.99 3868.41,4752 3868.41,4762 3855.94,4766.01
  region net PB11: 4334.98,4856.25 4340.97,4867.9 4333.9,4874.97 4322.25,4868.98
  region net PB10: 4279.23,4837.75 4287.28,4849.21 4282.39,4858.46 4270.81,4853.67
  region net ENCODER_R-A: 4512.24,5154.34 4523.18,5165.1 4521.26,5177.33 4509.45,5172.13
  region net ENCODER_R-B: 4490.94,5177.99 4500.37,5182 4500.37,5192 4490.94,5196.01
  region net L_EN_PWM: 5760.94,4822.99 5773.41,4827 5773.41,4837 5760.94,4841.01
  region net L_PH_DIR: 5745.06,4776.01 5732.59,4772 5732.59,4762 5745.06,4757.99
  region net R_EN_PWM: 5180.06,4841.01 5167.59,4837 5167.59,4827 5180.06,4822.99
  region net R_PH_DIR: 5195.94,4757.99 5208.41,4762 5208.41,4772 5195.94,4776.01
  region net L_EN_PWM: 4528.99,5109.06 4533,5096.59 4543,5096.59 4547.01,5109.06
  region net R_EN_PWM: 4563.99,5109.06 4568,5096.59 4578,5096.59 4582.01,5109.06
  region net L_PH_DIR: 4668.99,5114.06 4673,5101.59 4683,5101.59 4687.01,5114.06
  region net R_PH_DIR: 4703.99,5114.06 4708,5101.59 4718,5101.59 4722.01,5114.06
  region net AOUT_PH_DIR: 4733.75,4528.98 4722.1,4534.97 4715.03,4527.9 4721.02,4516.25
  region net AOUT_EN_PWM: 4688.75,4528.98 4677.1,4534.97 4670.03,4527.9 4676.02,4516.25
  region net AOUT_PH_DIR: 4633.99,4849.06 4638,4836.59 4648,4836.59 4652.01,4849.06
  region net AOUT_EN_PWM: 4603.99,4884.06 4608,4871.59 4618,4871.59 4622.01,4884.06
  region net ADC-SONAR-7: 4452.25,4350.02 4463.9,4344.03 4470.97,4351.1 4464.98,4362.75
  region net ADC-SONAR-6: 4417.25,4350.02 4428.9,4344.03 4435.97,4351.1 4429.98,4362.75
  region net ADC-SONAR-5: 4305.94,4422.99 4312.14,4427 4312.14,4437 4305.94,4441.01
  region net ADC-SONAR-4: 4257.25,4420.02 4268.9,4414.03 4275.97,4421.1 4269.98,4432.75
  region net ADC-SONAR-0: 4126.02,4482.75 4120.03,4471.1 4127.1,4464.03 4138.75,4470.02
  region net ADC-SONAR-1: 4161.02,4477.75 4155.03,4466.1 4162.1,4459.03 4173.75,4465.02
  region net ADC-SONAR-2: 4185.06,4456.01 4173,4452 4173,4442 4185.06,4437.99
  region net ADC-SONAR-3: 4195.06,4426.01 4183,4422 4183,4412 4195.06,4407.99
  region net ADC-SONAR-0: 3822.01,3609.94 3818,3622.41 3808,3622.41 3803.99,3609.94
  region net ADC-SONAR-1: 4079.98,3601.25 4085.97,3612.9 4078.9,3619.97 4067.25,3613.98
  region net ADC-SONAR-2: 4318.75,3613.98 4307.1,3619.97 4300.03,3612.9 4306.02,3601.25
  region net ADC-SONAR-3: 4553.75,3613.98 4542.1,3619.97 4535.03,3612.9 4541.02,3601.25
  region net ADC-SONAR-4: 4797.35,3609.6 4793.34,3622.07 4783.34,3622.07 4779.33,3609.6
  region net ADC-SONAR-5: 5052.01,3609.94 5048,3622.41 5038,3622.41 5033.99,3609.94
  region net ADC-SONAR-6: 5282.01,3609.94 5278,3622.41 5268,3622.41 5263.99,3609.94
  region net ADC-SONAR-7: 5529.09,3613.64 5517.44,3619.63 5510.37,3612.56 5516.36,3600.91
  region net B9: 3693.99,4494.06 3698,4481.59 3708,4481.59 3712.01,4494.06
  region net BOOT0: 3643.99,4499.06 3648,4486.59 3658,4486.59 3662.01,4499.06
  region net BOOT0: 3730.06,4121.01 3717.59,4117 3717.59,4107 3730.06,4102.99
  region net B9: 3650.94,3377.99 3663.41,3382 3663.41,3392 3650.94,3396.01
  region net RST: 4431.02,5622.75 4425.03,5611.1 4432.1,5604.03 4443.75,5610.02
  region net RST: 4145.94,4517.99 4158.41,4522 4158.41,4532 4145.94,4536.01
  region net VCC3V3: 4520.94,4402.99 4533.41,4407 4533.41,4417 4520.94,4421.01
  region net VCC3V3: 5371.47,5080.5 5385.87,5082 5390.45,5092 5378.97,5096.88
  region net VCC3V3: 6195.06,5096.01 6182.59,5092 6182.59,5082 6195.06,5077.99
  region net VCC3V3: 5460.06,5096.01 5447.59,5092 5447.59,5082 5460.06,5077.99
  region net VCC3V3: 5475.94,5077.99 5488.41,5082 5488.41,5092 5475.94,5096.01

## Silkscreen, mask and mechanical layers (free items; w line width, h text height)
Mechanical 1:
  circle w1 net "": c6454,3094 r59.06
  circle w1 net "": c3090,3094 r59.06
  circle w1 net "": c6454,5946 r59.06
  circle w1 net "": c3090,5946 r59.06
  lines w10 net "": 3000,3091.07 ccw(c3091,3091) 3182,3090.93 ; 3000,3092.14 3000,3168 3000,5872 3000,5947.86 ; 3000,5948.93 cw(c3091,5949) 3182,5949.07 ; 3182,3091 cw(c3271.32,3077.84) 3276,3168 ; 3182,5949 ccw(c3271.32,5962.16) 3276,5872 6272.56,5872 6272.68,5871.88 ; 3271.32,3168.12 3271.44,3168 6268,3168 cw(c6272.68,3077.84) 6362,3091 ; 6268,5872 ccw(c6272.68,5962.16) 6362,5949 ; 6362,3090.93 ccw(c6453,3091) 6544,3091.07 ; 6362,5949.07 cw(c6453,5949) 6544,5948.93 ; 6544,3092.14 6544,3168 6544,5872 6544,5947.86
